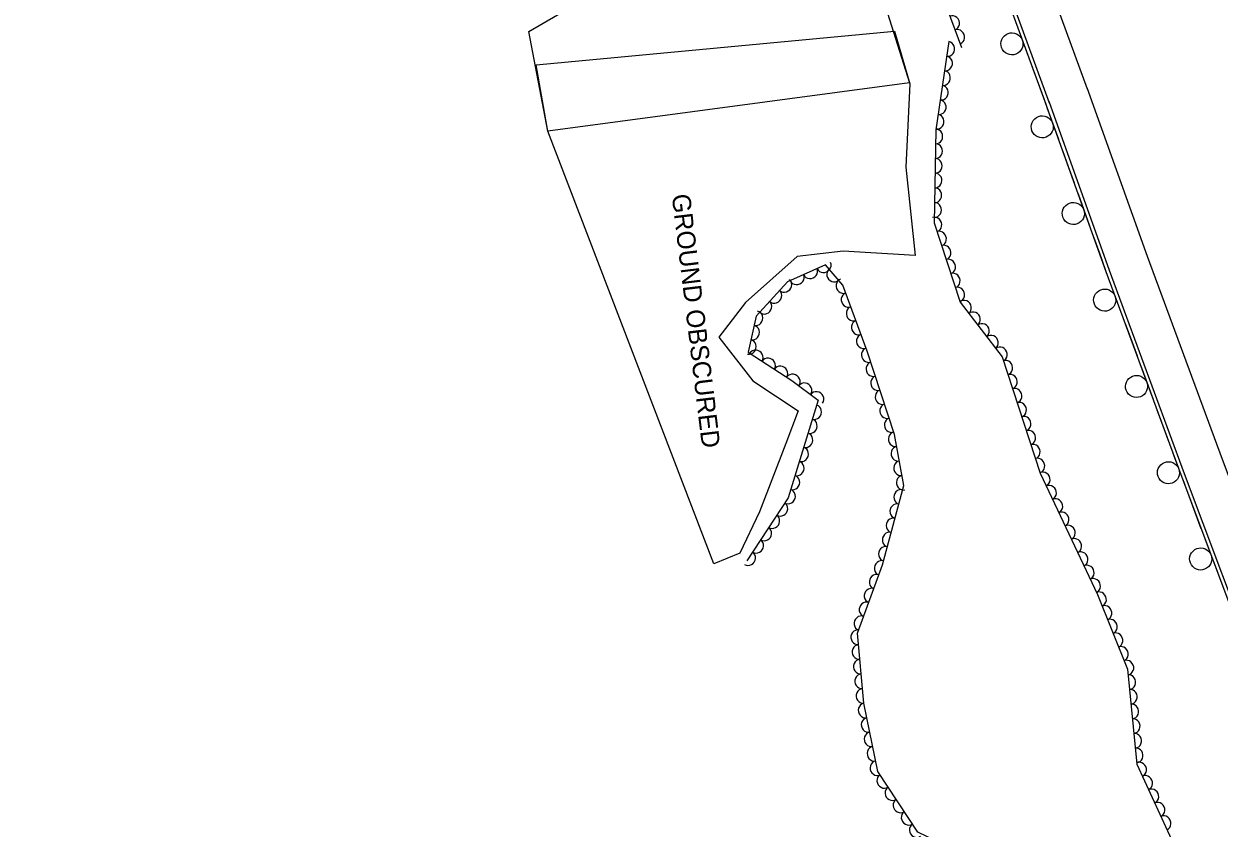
# Model space of a CAD drawing. Extents: x 1746719 to 1766531, y 631721 to 662391.
# Drawn here: x 1754164.2 to 1754489.1, y 649237.8 to 649456.3 of the extents above; entities that cross this region are included whole.
import ezdxf

# ---------------------------------------------------------------- set-up
doc = ezdxf.new("R2010")
doc.units = 0
for name, color, linetype in [('SURVEY - AERIAL SURVEY - Photo Control - Points - Elevations', 7, 'Continuous'), ('SURVEY - AERIAL SURVEY - Photo Control - Points - Locators', 7, 'Continuous'), ('SURVEY - AERIAL SURVEY - Photo Control - Points - Numbers', 7, 'Continuous'), ('SURVEY - AERIAL SURVEY - Photo Control with Text', 7, 'Continuous')]:
    doc.layers.add(name, color=color, linetype=linetype)

msp = doc.modelspace()

# ---------------------------------------------------------------- linework, layer by layer
at = {"layer": 'SURVEY - AERIAL SURVEY - Photo Control - Points - Elevations'}
for points in [[(1754298.66, 649872.79), (1754343.18, 649742.47), (1754374.58, 649653.49), (1754400.82, 649581.61), (1754453.23, 649438.62)], [(1754289.89, 649864.41), (1754332.79, 649738.86), (1754364.23, 649649.77), (1754390.49, 649577.83), (1754442.91, 649434.83)], [(1754453.1, 649438.99), (1754469.56, 649393.16), (1754489.93, 649338.01), (1754510.45, 649283.3), (1754511.64, 649280.19)], [(1754442.75, 649435.27), (1754459.22, 649389.39), (1754479.62, 649334.17), (1754500.16, 649279.4), (1754501.37, 649276.25)]]:
    msp.add_lwpolyline(points, dxfattribs=at)
at = {"layer": 'SURVEY - AERIAL SURVEY - Photo Control - Points - Locators'}
for points in [[(1754306.65, 649427.15), (1754301.44, 649454.25), (1754337.64, 649475.34), (1754332.91, 649530.99), (1754285.2, 649644.02), (1754238.76, 649749.99), (1754236.2, 649783.3), (1754205.23, 649865.29), (1754178.89, 649843.08), (1754164.2, 649889.48), (1754197.11, 649948.37), (1754220.8, 649913.17), (1754277.14, 649778.61), (1754332.9, 649656.66), (1754370.16, 649550.51), (1754404.93, 649440.26), (1754306.65, 649427.15)], [(1754400.8, 649454.28), (1754404.98, 649439.96), (1754403.96, 649417.33), (1754406.49, 649393.36), (1754386.88, 649394.56), (1754374.37, 649393.13), (1754360.33, 649380.58), (1754353.06, 649371.17), (1754362.36, 649359.3), (1754374.63, 649351.2), (1754371.34, 649342.31), (1754364.18, 649323.69), (1754358.78, 649312.5), (1754351.72, 649309.59), (1754306.65, 649427.15), (1754303.45, 649445.16), (1754400.8, 649454.28)]]:
    msp.add_lwpolyline(points, dxfattribs=at)
at = {"layer": 'SURVEY - AERIAL SURVEY - Photo Control - Points - Numbers'}
for points in [[(1754289.46, 649864.22), (1754331.85, 649738.54), (1754363.29, 649649.43), (1754389.55, 649577.48), (1754441.97, 649434.49)], [(1754434.01, 649456.19), (1754437.18, 649447.56)], [(1754438.28, 649444.55), (1754439.9, 649440.14)], [(1754439.9, 649440.14), (1754441.51, 649435.72)], [(1754441.81, 649434.93), (1754458.28, 649389.05), (1754478.68, 649333.82), (1754499.23, 649279.04), (1754500.43, 649275.89)], [(1754442.29, 649433.6), (1754445.4, 649424.94)], [(1754446.48, 649421.93), (1754448.06, 649417.51)], [(1754448.06, 649417.51), (1754449.65, 649413.08)], [(1754450.74, 649410.07), (1754453.84, 649401.41)], [(1754454.93, 649398.4), (1754456.52, 649393.98)], [(1754456.52, 649393.98), (1754458.1, 649389.55)], [(1754459.21, 649386.55), (1754462.4, 649377.92)], [(1754463.5, 649374.92), (1754465.13, 649370.51)], [(1754465.13, 649370.51), (1754466.76, 649366.1)], [(1754467.87, 649363.1), (1754471.05, 649354.47)], [(1754472.16, 649351.47), (1754473.79, 649347.06)], [(1754473.79, 649347.06), (1754475.42, 649342.65)], [(1754476.53, 649339.65), (1754478.68, 649333.82), (1754479.73, 649331.02)], [(1754480.85, 649328.03), (1754482.5, 649323.62)], [(1754482.5, 649323.62), (1754484.15, 649319.22)], [(1754485.28, 649316.23), (1754488.51, 649307.61)]]:
    msp.add_lwpolyline(points, dxfattribs=at)
for centre, start, end in [((1754432.76, 649450.88), 133.3982, 133.3842), ((1754441, 649428.3), 133.0247, 133.0107), ((1754449.45, 649404.77), 133.0247, 133.0107), ((1754457.97, 649381.24), 133.5357, 133.5217), ((1754466.63, 649357.79), 133.5357, 133.5217), ((1754475.29, 649334.33), 133.5357, 133.5217), ((1754484.07, 649310.91), 133.8289, 133.8149)]:
    msp.add_arc(centre, 3, start, end, dxfattribs=at)
at = {"layer": 'SURVEY - AERIAL SURVEY - Photo Control with Text'}
for points in [[(1754166.74, 649890.48), (1754176.87, 649920.51), (1754184.32, 649931.68), (1754190.2, 649940.32), (1754197.86, 649945.85), (1754217.64, 649930.63), (1754230.89, 649883.58), (1754250.56, 649822.66), (1754267.73, 649791.06), (1754289.59, 649743.11), (1754304.09, 649714.97), (1754325.28, 649673.97), (1754345.25, 649622.29), (1754363.86, 649587.9), (1754377.55, 649547.63), (1754396.42, 649515.54), (1754410.38, 649473.41), (1754419.07, 649449.85)], [(1754415.58, 649451.47), (1754412.08, 649427.47), (1754411.65, 649402.23), (1754418.7, 649380.66), (1754430.08, 649365.87), (1754440.44, 649334.26), (1754456.01, 649301.28), (1754464.15, 649280.95), (1754466.75, 649255.2), (1754481.28, 649223.44)], [(1754429.2, 649150.37), (1754435.12, 649169.01), (1754441.76, 649192.23), (1754440.06, 649210.76), (1754427.48, 649226.94), (1754407.15, 649236.72), (1754396.29, 649253.16), (1754392.48, 649271.75), (1754390.77, 649290.75), (1754397.58, 649309.31), (1754403.39, 649330.91), (1754400.81, 649344.74), (1754393.4, 649367.37), (1754386.77, 649385.33), (1754382.07, 649390.82), (1754371.76, 649386.21), (1754363.25, 649376.86), (1754361.03, 649367.1), (1754372.9, 649359.42), (1754380.12, 649354.1), (1754371.9, 649327.54), (1754360.66, 649310.36)]]:
    msp.add_lwpolyline(points, dxfattribs=at)
for centre, major_axis in [((1754416.61, 649456.51), (0.69, -1.88)), ((1754418, 649452.76), (0.69, -1.88)), ((1754415.3, 649449.49), (-0.29, -1.98)), ((1754414.72, 649445.53), (-0.29, -1.98)), ((1754414.14, 649441.57), (-0.29, -1.98)), ((1754413.56, 649437.61), (-0.29, -1.98)), ((1754412.98, 649433.66), (-0.29, -1.98)), ((1754412.4, 649429.7), (-0.29, -1.98)), ((1754412.05, 649425.72), (-0.03, -2)), ((1754411.98, 649421.72), (-0.03, -2)), ((1754411.91, 649417.72), (-0.03, -2)), ((1754411.84, 649413.72), (-0.03, -2)), ((1754411.77, 649409.72), (-0.03, -2)), ((1754411.71, 649405.73), (-0.03, -2)), ((1754411.8, 649401.75), (0.62, -1.9)), ((1754413.05, 649397.95), (0.62, -1.9)), ((1754414.29, 649394.15), (0.62, -1.9)), ((1754381.63, 649390.62), (-1.83, -0.82)), ((1754415.53, 649390.34), (0.62, -1.9)), ((1754370.96, 649385.33), (-1.35, -1.48)), ((1754374.32, 649387.36), (-1.83, -0.82)), ((1754377.98, 649388.99), (-1.83, -0.82)), ((1754384.36, 649388.15), (-1.3, 1.52)), ((1754386.87, 649385.06), (-0.69, 1.88)), ((1754416.78, 649386.54), (0.62, -1.9)), ((1754368.27, 649382.37), (-1.35, -1.48)), ((1754418.02, 649382.74), (0.62, -1.9)), ((1754365.57, 649379.41), (-1.35, -1.48)), ((1754388.26, 649381.3), (-0.69, 1.88)), ((1754419.8, 649379.22), (1.22, -1.59)), ((1754363.13, 649376.32), (-0.44, -1.95)), ((1754389.64, 649377.55), (-0.69, 1.88)), ((1754422.24, 649376.05), (1.22, -1.59)), ((1754362.24, 649372.42), (-0.44, -1.95)), ((1754391.03, 649373.8), (-0.69, 1.88)), ((1754424.68, 649372.88), (1.22, -1.59)), ((1754361.36, 649368.52), (-0.44, -1.95)), ((1754392.41, 649370.05), (-0.69, 1.88)), ((1754427.12, 649369.71), (1.22, -1.59)), ((1754363.17, 649365.72), (1.68, -1.09)), ((1754393.76, 649366.28), (-0.62, 1.9)), ((1754429.56, 649366.54), (1.22, -1.59)), ((1754366.53, 649363.55), (1.68, -1.09)), ((1754395, 649362.48), (-0.62, 1.9)), ((1754431.06, 649362.88), (0.62, -1.9)), ((1754369.88, 649361.37), (1.68, -1.09)), ((1754373.23, 649359.18), (1.61, -1.19)), ((1754432.3, 649359.08), (0.62, -1.9)), ((1754376.45, 649356.81), (1.61, -1.19)), ((1754396.25, 649358.68), (-0.62, 1.9)), ((1754433.55, 649355.27), (0.62, -1.9)), ((1754379.67, 649354.43), (1.61, -1.19)), ((1754397.49, 649354.88), (-0.62, 1.9)), ((1754379.1, 649350.82), (-0.59, -1.91)), ((1754398.74, 649351.07), (-0.62, 1.9)), ((1754434.8, 649351.47), (0.62, -1.9)), ((1754377.92, 649346.99), (-0.59, -1.91)), ((1754399.98, 649347.27), (-0.62, 1.9)), ((1754436.04, 649347.67), (0.62, -1.9)), ((1754376.74, 649343.17), (-0.59, -1.91)), ((1754401.06, 649343.43), (-0.37, 1.97)), ((1754437.29, 649343.87), (0.62, -1.9)), ((1754375.56, 649339.35), (-0.59, -1.91)), ((1754401.79, 649339.5), (-0.37, 1.97)), ((1754438.53, 649340.07), (0.62, -1.9)), ((1754439.78, 649336.27), (0.62, -1.9)), ((1754374.37, 649335.53), (-0.59, -1.91)), ((1754402.52, 649335.56), (-0.37, 1.97)), ((1754441.24, 649332.56), (0.85, -1.81)), ((1754373.19, 649331.71), (-0.59, -1.91)), ((1754403.26, 649331.63), (-0.37, 1.97)), ((1754372.01, 649327.89), (-0.59, -1.91)), ((1754402.54, 649327.76), (0.52, 1.93)), ((1754442.95, 649328.94), (0.85, -1.81)), ((1754369.91, 649324.5), (-1.09, -1.67)), ((1754401.5, 649323.89), (0.52, 1.93)), ((1754444.66, 649325.32), (0.85, -1.81)), ((1754367.72, 649321.15), (-1.09, -1.67)), ((1754400.47, 649320.03), (0.52, 1.93)), ((1754446.37, 649321.7), (0.85, -1.81)), ((1754365.53, 649317.8), (-1.09, -1.67)), ((1754448.07, 649318.09), (0.85, -1.81)), ((1754363.34, 649314.45), (-1.09, -1.67)), ((1754399.43, 649316.17), (0.52, 1.93)), ((1754449.78, 649314.47), (0.85, -1.81)), ((1754361.15, 649311.11), (-1.09, -1.67)), ((1754398.39, 649312.31), (0.52, 1.93)), ((1754451.49, 649310.85), (0.85, -1.81)), ((1754397.27, 649308.47), (0.69, 1.88)), ((1754453.2, 649307.24), (0.85, -1.81)), ((1754395.89, 649304.71), (0.69, 1.88)), ((1754454.91, 649303.62), (0.85, -1.81)), ((1754394.51, 649300.96), (0.69, 1.88)), ((1754456.54, 649299.97), (0.74, -1.86)), ((1754393.14, 649297.2), (0.69, 1.88)), ((1754391.76, 649293.45), (0.69, 1.88)), ((1754458.02, 649296.25), (0.74, -1.86)), ((1754459.51, 649292.54), (0.74, -1.86)), ((1754390.87, 649289.63), (-0.18, 1.99)), ((1754461, 649288.83), (0.74, -1.86)), ((1754391.23, 649285.64), (-0.18, 1.99)), ((1754462.48, 649285.11), (0.74, -1.86)), ((1754391.59, 649281.66), (-0.18, 1.99)), ((1754463.97, 649281.4), (0.74, -1.86)), ((1754391.94, 649277.68), (-0.18, 1.99)), ((1754464.5, 649277.45), (0.2, -1.99)), ((1754392.3, 649273.69), (-0.18, 1.99)), ((1754464.91, 649273.47), (0.2, -1.99)), ((1754392.89, 649269.74), (-0.4, 1.96)), ((1754465.31, 649269.49), (0.2, -1.99)), ((1754393.7, 649265.82), (-0.4, 1.96)), ((1754465.71, 649265.51), (0.2, -1.99)), ((1754394.5, 649261.91), (-0.4, 1.96)), ((1754466.11, 649261.53), (0.2, -1.99)), ((1754395.3, 649257.99), (-0.4, 1.96)), ((1754466.51, 649257.55), (0.2, -1.99)), ((1754396.11, 649254.07), (-0.4, 1.96)), ((1754467.43, 649253.71), (0.83, -1.82)), ((1754397.99, 649250.6), (-1.1, 1.67)), ((1754469.09, 649250.08), (0.83, -1.82)), ((1754400.19, 649247.26), (-1.1, 1.67)), ((1754470.76, 649246.44), (0.83, -1.82)), ((1754402.4, 649243.92), (-1.1, 1.67)), ((1754472.42, 649242.8), (0.83, -1.82)), ((1754404.6, 649240.58), (-1.1, 1.67)), ((1754474.08, 649239.16), (0.83, -1.82)), ((1754406.8, 649237.24), (-1.1, 1.67))]:
    msp.add_ellipse(centre, major_axis=major_axis, ratio=0.940188, start_param=0, end_param=3.141593, dxfattribs=at)

# ---------------------------------------------------------------- texts
at = {"layer": 'SURVEY - AERIAL SURVEY - Photo Control - Points - Locators'}
msp.add_text('GROUND OBSCURED', height=5, rotation=276.8506, dxfattribs=at).set_placement((1754340.28, 649409.79))

doc.saveas('drawing.dxf')
